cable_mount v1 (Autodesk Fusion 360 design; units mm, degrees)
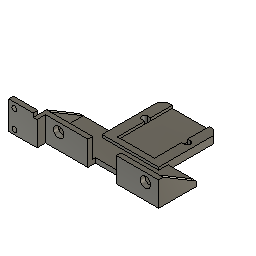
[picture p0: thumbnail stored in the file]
sketch "Sketch1" plane through (0, 0, 0) normal (0, 0, 1) x axis (1, 0, 0)
  line L1 (15, 47) -> (-15, 47)
  line L2 (15, 0) -> (15, 47)
  line L3 (-15, 0) -> (15, 0)
  line L4 (-15, 47) -> (-15, 0)
  line L5 (30, 20) -> (15, 20)
  line L6 (30, 0) -> (30, 20)
  line L7 (15, 0) -> (30, 0)
  line L8 (15, 20) -> (15, 0)
  line L9 (-30, 0) -> (-15, 0)
  line L10 (-30, 20) -> (-30, 0)
  line L11 (-15, 20) -> (-30, 20)
  line L12 (-15, 0) -> (-15, 20)
  point P6 (0, 0)
  point P1 (0, 0)
  point P7 (15, 20)
  point P4 (15, 0)
  point P10 (15, 0)
  point P13 (-15, 20)
  point P11 (-30, 0)
  point P12 (-30, 20)
  point P2 (-15, 47)
  point P5 (-15, 0)
  point P3 (15, 47)
  point P9 (30, 0)
  horizontal L1
  vertical L2
  horizontal L3
  vertical L4
  midpoint L3 P6
  coincident P1 P6
  horizontal L5
  vertical L6
  horizontal L7
  vertical L8
  coincident L2 P7
  coincident P4 P10
  horizontal L9
  vertical L10
  horizontal L11
  vertical L12
  horizontal P7 P13
  equal L7 L9
  dimension "d1" distance P11 P12 = 20
  dimension "d2" distance P2 P5 = 47
  dimension "d3" distance P2 P3 = 30
  dimension "d4" distance P9 P11 = 60
extrude "Extrude1" new body sketch "Sketch1" along normal blind 2.5
sketch "Sketch2" plane through (0, 0, 0) normal (0, -1, 0) x axis (1, 0, 0)
  line L1 (30, 0) -> (-30, 0)
  line L2 (30, 2.5) -> (30, 0)
  line L3 (-30, 2.5) -> (30, 2.5)
  line L4 (-30, 0) -> (-30, 2.5)
  line L5 (30, 2.5) -> (-30, 2.5)
  line L6 (30, 13) -> (30, 2.5)
  line L7 (-30, 13) -> (30, 13)
  line L8 (-30, 2.5) -> (-30, 13)
  point P5 (-30, 2.5)
  point P6 (-30, 2.5)
  point P4 (30, 2.5)
  point P7 (30, 2.5)
  point P3 (30, 0)
  point P8 (30, 13)
  horizontal L5
  vertical L6
  horizontal L7
  vertical L8
  coincident P5 P6
  coincident P4 P7
  dimension "d8" distance P3 P8 = 13
extrude "Extrude2" add sketch "Sketch2" profile of L3 L5 L6 L7 L8 against normal blind 2.5
sketch "Sketch3" plane through (30, 0, 0) normal (1, 0, 0) x axis (0, 1, 0)
  line L1 (20, 0) -> (0, 0)
  line L2 (20, 2.5) -> (20, 0)
  line L3 (2.5, 2.5) -> (20, 2.5)
  line L4 (2.5, 13) -> (2.5, 2.5)
  line L5 (0, 13) -> (2.5, 13)
  line L6 (0, 0) -> (0, 13)
  line L7 (20, 2.5) -> (2.5, 13)
  point P6 (2.5, 13)
  point P8 (2.5, 13)
  point P4 (20, 2.5)
  point P9 (20, 2.5)
  coincident P6 P8
  coincident P4 P9
extrude "Extrude3" add sketch "Sketch3" profile of L3 L4 L7 against normal blind 2
mirror "Mirror1" mirrorStitchTolerance 0.1
sketch "Sketch4" plane through (0, 2.5, 0) normal (0, 1, 0) x axis (-1, 0, 0)
  line L1 (28, 13) -> (28, 2.5)
  line L2 (-28, 13) -> (28, 13)
  line L3 (-28, 2.5) -> (-28, 13)
  line L4 (28, 2.5) -> (-28, 2.5)
  circle C1 centre (23, 8.5) radius 2.75
  point P1 (0, 0)
  point P6 (23, 8.5)
  point P7 (30, 0)
  dimension "d15" distance P1 P6 = 23
  dimension "d16" diameter C1 = 5.5
  dimension "d17" distance P6 P7 = 8.5
extrude "Extrude4" cut sketch "Sketch4" profile of C1 against normal blind 6
mirror "Mirror2" mirrorStitchTolerance 0.1
sketch "Sketch5" plane through (0, 0, 0) normal (0, -1, 0) x axis (1, 0, 0)
  line L1 (30, 0) -> (-30, 0)
  line L2 (30, 13) -> (30, 0)
  line L3 (-30, 13) -> (30, 13)
  line L4 (-30, 0) -> (-30, 13)
  line L5 (7.5, 0) -> (-7.5, 0)
  line L6 (7.5, 13) -> (7.5, 0)
  line L7 (-7.5, 13) -> (7.5, 13)
  line L8 (-7.5, 0) -> (-7.5, 13)
  circle C1 centre (23, 8.5) radius 2.75
  circle C2 centre (-23, 8.5) radius 2.75
  point P8 (-7.5, 0)
  point P12 (0, 0)
  point P1 (0, 0)
  point P10 (7.5, 13)
  point P9 (7.5, 0)
  horizontal L5
  vertical L6
  horizontal L7
  vertical L8
  coincident L1 P8
  midpoint L5 P12
  coincident P1 P12
  coincident L3 P10
  dimension "d22" distance P8 P9 = 15
extrude "Extrude5" cut sketch "Sketch5" profile of L1 L3 L5 L6 L7 L8 against normal blind 4
sketch "Sketch13" plane through (0, 0, 2.5) normal (0, 0, 1) x axis (-1, 0, 0)
  line L1 (-7.5, -2.5) -> (-7.5, -4)
  line L2 (-28, -2.5) -> (-7.5, -2.5)
  line L3 (-28, -20) -> (-28, -2.5)
  line L4 (-15, -20) -> (-28, -20)
  line L5 (-15, -47) -> (-15, -20)
  line L6 (15, -47) -> (-15, -47)
  line L7 (15, -20) -> (15, -47)
  line L8 (28, -20) -> (15, -20)
  line L9 (28, -2.5) -> (28, -20)
  line L10 (7.5, -2.5) -> (28, -2.5)
  line L11 (7.5, -4) -> (7.5, -2.5)
  line L12 (-7.5, -4) -> (7.5, -4)
  line L13 (-9.8, -47) -> (9.8, -47)
  line L14 (-9.8, -18) -> (-9.8, -47)
  line L15 (9.8, -18) -> (-9.8, -18)
  line L16 (9.8, -47) -> (9.8, -18)
  line L17 (15, -15) -> (15, -20)
  line L18 (-15, -15) -> (15, -15)
  line L19 (-15, -20) -> (-15, -15)
  point P14 (9.8, -47)
  point P18 (0, -47)
  point P1 (0, 0)
  point P9 (15, -20)
  point P19 (15, -20)
  point P6 (-15, -20)
  point P22 (-15, -20)
  point P15 (-9.8, -47)
  point P17 (9.8, -18)
  point P16 (-9.8, -18)
  horizontal L13
  vertical L14
  horizontal L15
  vertical L16
  coincident L6 P14
  midpoint L13 P18
  vertical P1 P18
  coincident P9 P19
  perpendicular L8 L17
  perpendicular L17 L18
  coincident P6 P22
  vertical L19
  dimension "d61" distance P14 P15 = 19.6
  dimension "d62" distance P9 P17 = 2
  dimension "d63" distance P16 L18 = 3
extrude "Extrude12" add sketch "Sketch13" profile of L5 L6 L7 L14 L15 L16 L17 L18 L19 along normal blind 1.4
offset_faces "OffsetFaces1" distance 2
offset_faces "OffsetFaces2" distance -2
sketch "Sketch9" plane through (-32, 0, 0) normal (-1, 0, 0) x axis (0, -1, 0)
  line L1 (0, 0) -> (-20, 0)
  line L2 (0, 13) -> (0, 0)
  line L3 (-2.5, 13) -> (0, 13)
  line L4 (-20, 2.5) -> (-2.5, 13)
  line L5 (-20, 0) -> (-20, 2.5)
  line L6 (4.5, 13) -> (0, 13)
  line L7 (4.5, 0) -> (4.5, 13)
  line L8 (0, 0) -> (4.5, 0)
  line L9 (0, 13) -> (0, 0)
  point P4 (0, 13)
  point P7 (0, 13)
  point P1 (0, 0)
  point P10 (0, 0)
  point P9 (4.5, 0)
  horizontal L6
  vertical L7
  horizontal L8
  vertical L9
  coincident P4 P7
  coincident P1 P10
  dimension "d43" distance P9 P10 = 4.5
extrude "Extrude8" add sketch "Sketch9" profile of L2 L6 L7 L8 L9 against normal blind 2
sketch "Sketch10" plane through (-32, 0, 0) normal (-1, 0, 0) x axis (0, -1, 0)
  line L1 (4.5, 0) -> (-20, 0)
  line L2 (4.5, 13) -> (4.5, 0)
  line L3 (-2.5, 13) -> (4.5, 13)
  line L4 (-20, 2.5) -> (-2.5, 13)
  line L5 (-20, 0) -> (-20, 2.5)
  line L6 (2, 13) -> (4.5, 13)
  line L7 (2, 0) -> (2, 13)
  line L8 (4.5, 0) -> (2, 0)
  line L9 (4.5, 13) -> (4.5, 0)
  point P9 (2, 0)
  point P4 (4.5, 13)
  point P7 (4.5, 13)
  point P8 (2, 13)
  horizontal L6
  vertical L7
  horizontal L8
  vertical L9
  coincident L1 P9
  coincident P4 P7
  dimension "d46" distance P7 P8 = 2.5
extrude "Extrude9" add sketch "Sketch10" profile of L1 L2 L3 L6 L7 L8 L9 along normal blind 13
sketch "Sketch12" plane through (0, 0, 13) normal (0, 0, 1) x axis (-1, 0, 0)
  line L1 (30, -2.5) -> (7.5, -2.5)
  line L2 (32, -2.5) -> (30, -2.5)
  line L3 (32, 2) -> (32, -2.5)
  line L4 (45, 2) -> (32, 2)
  line L5 (45, 4.5) -> (45, 2)
  line L6 (30, 4.5) -> (45, 4.5)
  line L7 (30, 0) -> (30, 4.5)
  line L8 (7.5, 0) -> (30, 0)
  line L9 (7.5, -2.5) -> (7.5, 0)
  line L10 (32, 4.5) -> (32, 2)
  point P5 (32, 2)
  point P11 (32, 2)
  point P12 (32, 4.5)
  coincident P5 P11
  coincident L6 P12
  perpendicular L6 L10
extrude "Extrude11" add sketch "Sketch12" profile of L4 L5 L6 L10 along normal blind 2
sketch "Sketch11" plane through (0, -2, 0) normal (0, 1, 0) x axis (-1, 0, 0)
  line L1 (32, 0) -> (32, 13)
  line L2 (45, 0) -> (32, 0)
  line L3 (45, 15) -> (45, 0)
  line L4 (32, 15) -> (45, 15)
  line L5 (32, 13) -> (32, 15)
  circle C1 centre (42, 2.5) radius 1.3
  circle C2 centre (42, 12) radius 1.3
  point P6 (42, 2.5)
  point P7 (42, 12)
  point P8 (30, 13)
  point P4 (45, 0)
  vertical P6 P7
  dimension "d49" diameter C1 = 2.6
  dimension "d50" diameter C2 = 2.6
  dimension "d51" distance P6 P7 = 9.5
  dimension "d55" distance P6 P8 = 12
  dimension "d58" distance P4 P6 = 2.5
extrude "Extrude10" cut sketch "Sketch11" profile of C1 C2 against normal blind 4
sketch "Sketch14" plane through (0, 0, 3.9) normal (0, 0, 1) x axis (-1, 0, 0)
  line L1 (-15, -47) -> (-15, -15)
  line L2 (-9.8, -47) -> (-15, -47)
  line L3 (-9.8, -18) -> (-9.8, -47)
  line L4 (9.8, -18) -> (-9.8, -18)
  line L5 (9.8, -47) -> (9.8, -18)
  line L6 (15, -47) -> (9.8, -47)
  line L7 (15, -15) -> (15, -47)
  line L8 (-15, -15) -> (15, -15)
  line L9 (11.4, -35.6) -> (9.8, -35.6)
  line L10 (9.8, -32.4) -> (11.4, -32.4)
  arc A1 centre (11.4, -34) radius 1.6 clockwise from (11.4, -32.4) to (11.4, -35.6)
  point P10 (9.8, -35.6)
  point P14 (9.8, -32.4)
  point P6 (9.8, -18)
  point P13 (11.4, -34)
  tangent L9 A1
  tangent A1 L10
  horizontal L9
  vertical P10 P14
  coincident L5 P10
  horizontal L10
  dimension "d66" distance P6 P13 = 16
  dimension "d67" radius A1 = 1.6 (= "( 3.2 / 2 ) * 1 mm")
  dimension "d68" distance P10 P13 = 1.6 (= "( 3.2 / 2 ) * 1 mm")
extrude "Extrude13" cut sketch "Sketch14" profile of L5 L9 A1 L10 against normal blind 9
mirror "Mirror4" mirrorStitchTolerance 0.1
chamfer "Chamfer2" distance 3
